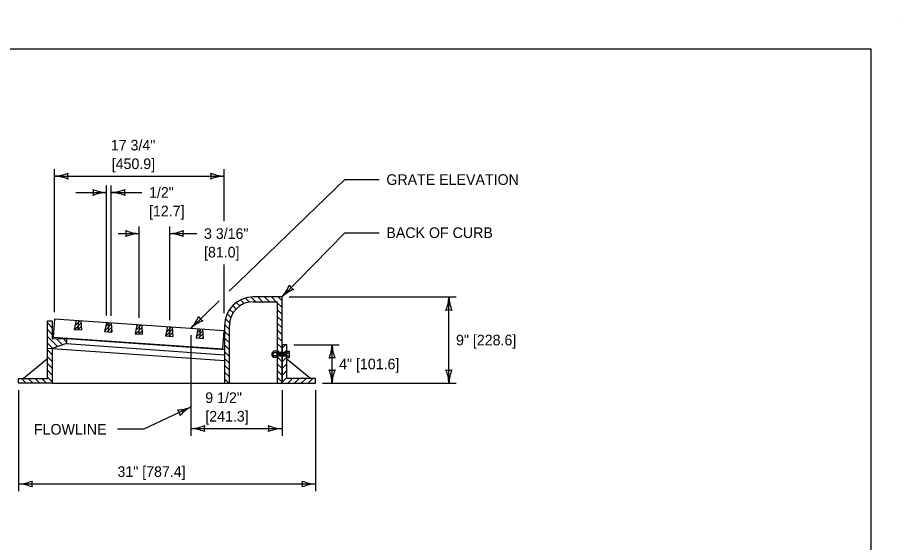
# Model space of a CAD drawing. Extents: x 49991.4 to 50057, y 49987.6 to 50011.4.
# Drawn here: x 50011.925 to 50016.9, y 49996.209 to 49999.176 of the extents above; entities that cross this region are included whole.
import ezdxf

# ---------------------------------------------------------------- set-up
doc = ezdxf.new("R2010")
doc.units = 0
for name, color, linetype in [('Level 1', 7, 'Continuous'), ('Level 2', 7, 'Continuous'), ('Level 3', 7, 'Continuous')]:
    doc.layers.add(name, color=color, linetype=linetype)

msp = doc.modelspace()

# ---------------------------------------------------------------- linework, layer by layer
at = {"layer": 'Level 1'}
for p, q in [((50016.9001, 49999.1756), (50016.9001, 49999.1756)), ((50013.1859, 49997.5794), (50013.2063, 49997.5589)), ((50013.2135, 49997.5901), (50013.2361, 49997.5674)), ((50013.246, 49997.5959), (50013.2726, 49997.5692)), ((50013.2838, 49997.5963), (50013.3109, 49997.5692)), ((50013.3221, 49997.5963), (50013.3492, 49997.5692)), ((50013.3604, 49997.5963), (50013.3875, 49997.5692)), ((50013.3987, 49997.5963), (50013.4206, 49997.5744)), ((50013.1243, 49997.526), (50013.1439, 49997.5065)), ((50013.1416, 49997.5471), (50013.1607, 49997.5279)), ((50013.1621, 49997.5649), (50013.1815, 49997.5455)), ((50013.3936, 49997.5632), (50013.4206, 49997.5361)), ((50013.1104, 49997.5016), (50013.1312, 49997.4809)), ((50013.3936, 49997.5249), (50013.4206, 49997.4978)), ((50013.3936, 49997.4866), (50013.4206, 49997.4595)), ((50012.0936, 49997.4497), (50012.1206, 49997.4226)), ((50012.2558, 49997.4626), (50012.2455, 49997.4124)), ((50012.2483, 49997.4122), (50012.2836, 49997.4475)), ((50012.2496, 49997.4327), (50012.2779, 49997.461)), ((50012.2546, 49997.4568), (50012.2601, 49997.4623)), ((50012.2693, 49997.4616), (50012.2657, 49997.411)), ((50012.2662, 49997.4109), (50012.2847, 49997.4295)), ((50012.2828, 49997.4607), (50012.286, 49997.4095)), ((50012.428, 49997.4505), (50012.4177, 49997.4003)), ((50012.4186, 49997.4049), (50012.4554, 49997.4417)), ((50012.4236, 49997.429), (50012.444, 49997.4494)), ((50012.4415, 49997.4496), (50012.438, 49997.3989)), ((50012.455, 49997.4486), (50012.4582, 49997.3975)), ((50012.6002, 49997.4385), (50012.5899, 49997.3883)), ((50012.594, 49997.408), (50012.6229, 49997.4369)), ((50012.5989, 49997.432), (50012.605, 49997.4381)), ((50012.6137, 49997.4375), (50012.6102, 49997.3869)), ((50012.6272, 49997.4366), (50012.6305, 49997.3855)), ((50012.7725, 49997.4264), (50012.7622, 49997.3762)), ((50012.7716, 49997.4221), (50012.7757, 49997.4262)), ((50013.0957, 49997.4397), (50013.1227, 49997.4127)), ((50013.1005, 49997.4732), (50013.1237, 49997.45)), ((50013.3936, 49997.4483), (50013.4206, 49997.4212)), ((50012.0936, 49997.4114), (50012.1206, 49997.3843)), ((50012.2455, 49997.4124), (50012.286, 49997.4095)), ((50012.2841, 49997.4097), (50012.2859, 49997.4115)), ((50012.4177, 49997.4003), (50012.4582, 49997.3975)), ((50012.4322, 49997.3993), (50012.4566, 49997.4237)), ((50012.4501, 49997.3981), (50012.4577, 49997.4057)), ((50012.5899, 49997.3883), (50012.6305, 49997.3855)), ((50012.5932, 49997.3881), (50012.6281, 49997.4229)), ((50012.6111, 49997.3868), (50012.6292, 49997.4049)), ((50012.629, 49997.3856), (50012.6304, 49997.3869)), ((50012.7639, 49997.3761), (50012.8002, 49997.4124)), ((50012.7666, 49997.398), (50012.7936, 49997.4249)), ((50012.7818, 49997.3749), (50012.8014, 49997.3944)), ((50012.786, 49997.4255), (50012.7824, 49997.3748)), ((50012.7995, 49997.4245), (50012.8027, 49997.3734)), ((50012.7997, 49997.3736), (50012.8025, 49997.3764)), ((50012.9447, 49997.4144), (50012.9344, 49997.3642)), ((50012.9353, 49997.3687), (50012.9722, 49997.4055)), ((50012.9403, 49997.3928), (50012.9608, 49997.4133)), ((50012.949, 49997.3632), (50012.9733, 49997.3875)), ((50012.9582, 49997.4134), (50012.9547, 49997.3628)), ((50012.9717, 49997.4125), (50012.9749, 49997.3614)), ((50013.0956, 49997.4015), (50013.1227, 49997.3744)), ((50013.3936, 49997.41), (50013.4206, 49997.3829)), ((50012.0936, 49997.3731), (50012.1513, 49997.3154)), ((50012.0936, 49997.3348), (50012.1226, 49997.3058)), ((50012.1452, 49997.3598), (50012.18, 49997.325)), ((50012.1828, 49997.3605), (50012.2019, 49997.3414)), ((50012.2019, 49997.3608), (50012.2019, 49997.3608)), ((50012.2019, 49997.3608), (50013.0956, 49997.2983)), ((50012.2019, 49997.3323), (50013.0956, 49997.2698)), ((50012.2679, 49997.3275), (50012.2679, 49997.3275)), ((50012.7622, 49997.3762), (50012.8027, 49997.3734)), ((50012.9344, 49997.3642), (50012.9749, 49997.3614)), ((50012.9669, 49997.3619), (50012.9744, 49997.3695)), ((50013.0956, 49997.3632), (50013.1227, 49997.3361)), ((50013.3936, 49997.3717), (50013.4206, 49997.3446)), ((50013.3936, 49997.3334), (50013.4206, 49997.3063)), ((50012.0936, 49997.3071), (50013.0956, 49997.237)), ((50012.0936, 49997.2965), (50012.1206, 49997.2694)), ((50013.0956, 49997.3249), (50013.1227, 49997.2978)), ((50013.0956, 49997.2866), (50013.1227, 49997.2595)), ((50013.3627, 49997.2781), (50013.3627, 49997.2646)), ((50013.3628, 49997.2781), (50013.3661, 49997.2815)), ((50013.3644, 49997.2781), (50013.3644, 49997.2646)), ((50013.3661, 49997.2815), (50013.3661, 49997.2612)), ((50013.3695, 49997.2815), (50013.3661, 49997.2815)), ((50013.3678, 49997.2781), (50013.3678, 49997.2646)), ((50013.3695, 49997.2581), (50013.3695, 49997.2845)), ((50013.3695, 49997.2815), (50013.3695, 49997.2612)), ((50013.3927, 49997.2889), (50013.3718, 49997.2889)), ((50013.3927, 49997.2801), (50013.3718, 49997.2801)), ((50013.3927, 49997.2537), (50013.3927, 49997.2889)), ((50013.3936, 49997.2865), (50013.3927, 49997.2865)), ((50013.3936, 49997.2951), (50013.4206, 49997.268)), ((50013.3936, 49997.2561), (50013.3936, 49997.2865)), ((50013.4477, 49997.2815), (50013.3936, 49997.2815)), ((50013.3949, 49997.2781), (50013.3949, 49997.2646)), ((50013.3966, 49997.2815), (50013.3966, 49997.2612)), ((50013.3983, 49997.2781), (50013.3983, 49997.2646)), ((50013.4, 49997.2815), (50013.4, 49997.2612)), ((50013.4017, 49997.2781), (50013.4017, 49997.2646)), ((50013.4033, 49997.2815), (50013.4033, 49997.2612)), ((50013.405, 49997.2781), (50013.405, 49997.2646)), ((50013.4067, 49997.2815), (50013.4067, 49997.2612)), ((50013.4084, 49997.2781), (50013.4084, 49997.2646)), ((50013.4101, 49997.2815), (50013.4101, 49997.2612)), ((50013.4118, 49997.2781), (50013.4118, 49997.2646)), ((50013.4135, 49997.2815), (50013.4135, 49997.2612)), ((50013.4152, 49997.2781), (50013.4152, 49997.2646)), ((50013.4169, 49997.2815), (50013.4169, 49997.2612)), ((50013.4186, 49997.2781), (50013.4186, 49997.2646)), ((50013.4203, 49997.2815), (50013.4203, 49997.2612)), ((50013.4206, 49997.3062), (50013.4399, 49997.3255)), ((50013.4206, 49997.2679), (50013.4477, 49997.295)), ((50013.422, 49997.2781), (50013.422, 49997.2646)), ((50013.4237, 49997.2815), (50013.4237, 49997.2612)), ((50013.4254, 49997.2781), (50013.4254, 49997.2646)), ((50013.427, 49997.2815), (50013.427, 49997.2612)), ((50013.4287, 49997.2781), (50013.4287, 49997.2646)), ((50013.4304, 49997.2815), (50013.4304, 49997.2612)), ((50013.4321, 49997.2781), (50013.4321, 49997.2646)), ((50013.4338, 49997.2815), (50013.4338, 49997.2612)), ((50013.4355, 49997.2781), (50013.4355, 49997.2646)), ((50013.4372, 49997.2815), (50013.4372, 49997.2612)), ((50013.4389, 49997.2781), (50013.4389, 49997.2646)), ((50013.4406, 49997.2815), (50013.4406, 49997.2612)), ((50013.4423, 49997.2781), (50013.4423, 49997.2646)), ((50013.444, 49997.2815), (50013.444, 49997.2612)), ((50013.4457, 49997.2781), (50013.4457, 49997.2646)), ((50013.4477, 49997.2561), (50013.4477, 49997.2865)), ((50013.4477, 49997.2865), (50013.4486, 49997.2865)), ((50013.4486, 49997.2889), (50013.4613, 49997.2889)), ((50013.4486, 49997.2537), (50013.4486, 49997.2889)), ((50013.4486, 49997.2801), (50013.4613, 49997.2801)), ((50013.4637, 49997.2581), (50013.4637, 49997.2845)), ((50012.0936, 49997.247), (50011.9581, 49997.1359)), ((50012.0936, 49997.2582), (50012.1206, 49997.2311)), ((50013.0956, 49997.2483), (50013.1227, 49997.2212)), ((50013.3628, 49997.2645), (50013.3661, 49997.2612)), ((50013.3695, 49997.2612), (50013.3661, 49997.2612)), ((50013.3927, 49997.2625), (50013.3718, 49997.2625)), ((50013.3927, 49997.2537), (50013.3718, 49997.2537)), ((50013.3936, 49997.2561), (50013.3927, 49997.2561)), ((50013.4477, 49997.2612), (50013.3936, 49997.2612)), ((50013.3936, 49997.2568), (50013.4206, 49997.2297)), ((50013.4206, 49997.2296), (50013.4477, 49997.2567)), ((50013.4477, 49997.2561), (50013.4486, 49997.2561)), ((50013.4477, 49997.247), (50013.4477, 49997.247)), ((50013.4477, 49997.247), (50013.5831, 49997.1359)), ((50013.4486, 49997.2625), (50013.4613, 49997.2625)), ((50013.4486, 49997.2537), (50013.4613, 49997.2537)), ((50012.0936, 49997.2199), (50012.1206, 49997.1928)), ((50012.0936, 49997.1816), (50012.1206, 49997.1545)), ((50013.0956, 49997.21), (50013.1227, 49997.1829)), ((50013.3936, 49997.2185), (50013.4206, 49997.1914)), ((50013.3936, 49997.1802), (50013.4206, 49997.1531)), ((50013.4206, 49997.1913), (50013.4477, 49997.2184)), ((50013.4206, 49997.153), (50013.4477, 49997.1801)), ((50011.9477, 49997.1359), (50011.9748, 49997.1088)), ((50011.9581, 49997.1359), (50011.9581, 49997.1359)), ((50011.986, 49997.1359), (50012.0131, 49997.1088)), ((50012.0244, 49997.1359), (50012.0514, 49997.1088)), ((50012.0627, 49997.1359), (50012.0897, 49997.1088)), ((50012.0936, 49997.1433), (50012.1206, 49997.1162)), ((50013.0956, 49997.1717), (50013.1227, 49997.1446)), ((50013.0956, 49997.1334), (50013.1202, 49997.1088)), ((50013.3936, 49997.1419), (50013.4206, 49997.1148)), ((50013.4206, 49997.1147), (50013.4477, 49997.1418)), ((50013.4531, 49997.1088), (50013.4801, 49997.1359)), ((50013.4914, 49997.1088), (50013.5184, 49997.1359)), ((50013.5297, 49997.1088), (50013.5567, 49997.1359)), ((50013.568, 49997.1088), (50013.595, 49997.1359)), ((50013.5831, 49997.1359), (50013.5831, 49997.1359)), ((50011.9311, 49997.1143), (50011.9365, 49997.1088)), ((50011.9311, 49997.1143), (50011.9365, 49997.1088)), ((50011.9311, 49997.1088), (50011.9311, 49997.1088)), ((50012.1206, 49997.1088), (50013.4206, 49997.1088)), ((50013.6063, 49997.1088), (50013.6102, 49997.1128))]:
    msp.add_line(p, q, dxfattribs=at)
for points in [[(49999.3835, 49998.9992), (50016.7501, 49998.9992), (50016.7501, 49987.7988), (49999.3835, 49987.7988)], [(50012.1206, 49997.3052), (50012.1206, 49997.1088), (50011.9311, 49997.1088), (50011.9311, 49997.1359), (50012.0936, 49997.1359), (50012.0936, 49997.4609), (50012.1206, 49997.4609), (50012.1206, 49997.3593), (50012.2019, 49997.3608), (50012.2019, 49997.3323)], [(50013.0933, 49997.404), (50012.1342, 49997.4711), (50012.1271, 49997.3697), (50013.0862, 49997.3027)], [(50013.4477, 49997.1359), (50013.4477, 49997.3255), (50013.4206, 49997.3255), (50013.4206, 49997.1088), (50013.6102, 49997.1088), (50013.6102, 49997.1359)]]:
    msp.add_lwpolyline(points, close=True, dxfattribs=at)
for points in [[(50013.2581, 49997.5692), (50013.3936, 49997.5692), (50013.3936, 49997.1088), (50013.4206, 49997.1088), (50013.4206, 49997.5963), (50013.2581, 49997.5963)], [(50013.0956, 49997.4338), (50013.0956, 49997.1088), (50013.1227, 49997.1088), (50013.1227, 49997.4338)]]:
    msp.add_lwpolyline(points, dxfattribs=at)
for centre, radius, start, end in [((50013.2581, 49997.4338), 0.1625, 90, 180), ((50013.2581, 49997.4338), 0.1354, 90, 180), ((50013.3748, 49997.2845), 0.00528, 123.6844, 236.3156), ((50013.3871, 49997.2713), 0.0176, 150.0207, 209.9793), ((50013.4584, 49997.2845), 0.00528, 303.6844, 56.3156), ((50013.4461, 49997.2713), 0.0176, 330.0207, 29.9793), ((50013.3748, 49997.2581), 0.00528, 123.6376, 236.3624), ((50013.4584, 49997.2581), 0.00528, 303.6376, 56.3624)]:
    msp.add_arc(centre, radius, start, end, dxfattribs=at)
at = {"layer": 'Level 3'}
for p, q in [((50012.1342, 49997.5111), (50012.1342, 49998.3194)), ((50012.1342, 49998.2794), (50013.0933, 49998.2794)), ((50013.0933, 49998.0244), (50013.0933, 49998.3194)), ((50012.428, 49997.4905), (50012.428, 49998.2271)), ((50012.455, 49997.4886), (50012.455, 49998.2271)), ((50013.1223, 49997.6292), (50013.7756, 49998.2598)), ((50013.7756, 49998.2598), (50013.9706, 49998.2598)), ((50012.2546, 49998.1871), (50012.428, 49998.1871)), ((50012.455, 49998.1871), (50012.6285, 49998.1871)), ((50012.6137, 49997.4775), (50012.6137, 49997.9944)), ((50012.786, 49997.4655), (50012.786, 49997.9944)), ((50012.495, 49997.9544), (50012.6137, 49997.9544)), ((50012.786, 49997.9544), (50012.9394, 49997.9544)), ((50013.7756, 49997.9595), (50013.4206, 49997.5963)), ((50013.7756, 49997.9595), (50013.9706, 49997.9595)), ((50013.0933, 49997.504), (50013.0933, 49997.7794)), ((50013.4606, 49997.5963), (50014.4044, 49997.5963)), ((50014.3644, 49997.1088), (50014.3644, 49997.5963)), ((50012.9061, 49997.4205), (50013.0648, 49997.5737)), ((50012.9061, 49996.8118), (50012.9061, 49997.3805)), ((50013.4877, 49997.3255), (50013.7433, 49997.3255)), ((50013.7033, 49997.1088), (50013.7033, 49997.3255)), ((50013.6502, 49997.1088), (50014.4044, 49997.1088)), ((50011.9311, 49997.0688), (50011.9311, 49996.4988)), ((50013.4206, 49997.0688), (50013.4206, 49996.8118)), ((50013.6102, 49997.0688), (50013.6102, 49996.4988)), ((50012.9061, 49996.9747), (50012.6399, 49996.8479)), ((50012.6399, 49996.8479), (50012.4911, 49996.8479)), ((50012.9061, 49996.8518), (50013.4206, 49996.8518)), ((50011.9311, 49996.5388), (50013.6102, 49996.5388))]:
    msp.add_line(p, q, dxfattribs=at)
for centre, radius, start, end in [((50012.1227, 49998.5121), 0.233, 272.8273, 292.0772), ((50012.125, 49998.0572), 0.2223, 67.456, 87.6395), ((50012.2624, 49998.2794), 0.0548, 162.1388, 197.8612), ((50013.1025, 49998.5015), 0.2223, 247.456, 267.6395), ((50012.9651, 49998.2794), 0.0548, 342.1388, 17.8612), ((50013.1048, 49998.0466), 0.233, 92.8273, 112.0772), ((50012.4372, 49998.4092), 0.2223, 247.456, 267.6395), ((50012.2998, 49998.1871), 0.0548, 342.1388, 17.8612), ((50012.4395, 49997.9543), 0.233, 92.8273, 112.0772), ((50012.4435, 49998.4198), 0.233, 272.8273, 292.0772), ((50012.4459, 49997.9649), 0.2223, 67.456, 87.6395), ((50012.5832, 49998.1871), 0.0548, 162.1388, 197.8612), ((50012.6229, 49998.1766), 0.2223, 247.456, 267.6395), ((50012.4855, 49997.9544), 0.0548, 342.1388, 17.8612), ((50012.6252, 49997.7217), 0.233, 92.8273, 112.0772), ((50012.7745, 49998.1871), 0.233, 272.8273, 292.0772), ((50012.7768, 49997.7323), 0.2223, 67.456, 87.6395), ((50012.9142, 49997.9544), 0.0548, 162.1388, 197.8612), ((50013.2462, 49997.7508), 0.233, 318.4827, 337.7326), ((50013.5731, 49997.4345), 0.2223, 113.1114, 133.2949), ((50013.5103, 49997.688), 0.0548, 207.7942, 243.5166), ((50014.1422, 49997.6055), 0.2223, 337.456, 357.6395), ((50014.5971, 49997.6078), 0.233, 182.8273, 202.0772), ((50012.7362, 49997.5799), 0.233, 316.8137, 336.0635), ((50012.9983, 49997.5095), 0.0548, 206.1252, 241.8475), ((50014.3644, 49997.4681), 0.0548, 72.1388, 107.8612), ((50013.0537, 49997.2543), 0.2223, 111.4424, 131.6259), ((50013.4812, 49997.3346), 0.2223, 337.456, 357.6395), ((50013.936, 49997.337), 0.233, 182.8273, 202.0772), ((50013.7033, 49997.1973), 0.0548, 72.1388, 107.8612), ((50013.7033, 49997.237), 0.0548, 252.1388, 287.8612), ((50013.4706, 49997.0973), 0.233, 2.8273, 22.0772), ((50013.9255, 49997.0997), 0.2223, 157.456, 177.6395), ((50014.3644, 49997.237), 0.0548, 252.1388, 287.8612), ((50014.1316, 49997.0973), 0.233, 2.8273, 22.0772), ((50014.5865, 49997.0997), 0.2223, 157.456, 177.6395), ((50012.8189, 49997.1792), 0.2223, 272.9102, 293.0937), ((50012.7903, 49996.9195), 0.0548, 7.593, 43.3154), ((50013.0165, 49996.7695), 0.233, 118.2815, 137.5314), ((50012.8946, 49997.0845), 0.233, 272.8273, 292.0772), ((50012.8969, 49996.6296), 0.2223, 67.456, 87.6395), ((50013.0343, 49996.8518), 0.0548, 162.1388, 197.8612), ((50013.4298, 49997.0739), 0.2223, 247.456, 267.6395), ((50013.2924, 49996.8518), 0.0548, 342.1388, 17.8612), ((50013.4321, 49996.6191), 0.233, 92.8273, 112.0772), ((50011.9196, 49996.7715), 0.233, 272.8273, 292.0772), ((50011.9219, 49996.3167), 0.2223, 67.456, 87.6395), ((50012.0593, 49996.5388), 0.0548, 162.1388, 197.8612), ((50013.6194, 49996.7609), 0.2223, 247.456, 267.6395), ((50013.482, 49996.5388), 0.0548, 342.1388, 17.8612), ((50013.6217, 49996.3061), 0.233, 92.8273, 112.0772)]:
    msp.add_arc(centre, radius, start, end, dxfattribs=at)

# ---------------------------------------------------------------- texts
at = {"layer": 'Level 2'}
for s, p in [('17 3/4"', (50012.4526, 49998.4244)), ('[450.9]', (50012.4576, 49998.3194)), ('GRATE ELEVATION ', (50014.0106, 49998.2298)), ('1/2"', (50012.6685, 49998.1571)), ('[12.7]', (50012.6685, 49998.0521)), ('3 3/16"', (50012.9794, 49997.9244)), ('BACK OF CURB', (50014.0106, 49997.9295)), ('[81.0]', (50012.9794, 49997.8194)), ('9" [228.6]', (50014.4044, 49997.3226)), ('4" [101.6]', (50013.7433, 49997.1872)), ('9 1/2"', (50012.9867, 49996.9968)), ('[241.3]', (50012.9867, 49996.8918)), ('FLOWLINE', (50012.0179, 49996.8179)), ('31" [787.4]', (50012.4901, 49996.5788))]:
    msp.add_text(s, height=0.06, dxfattribs=at).set_placement(p)

doc.saveas('drawing.dxf')
